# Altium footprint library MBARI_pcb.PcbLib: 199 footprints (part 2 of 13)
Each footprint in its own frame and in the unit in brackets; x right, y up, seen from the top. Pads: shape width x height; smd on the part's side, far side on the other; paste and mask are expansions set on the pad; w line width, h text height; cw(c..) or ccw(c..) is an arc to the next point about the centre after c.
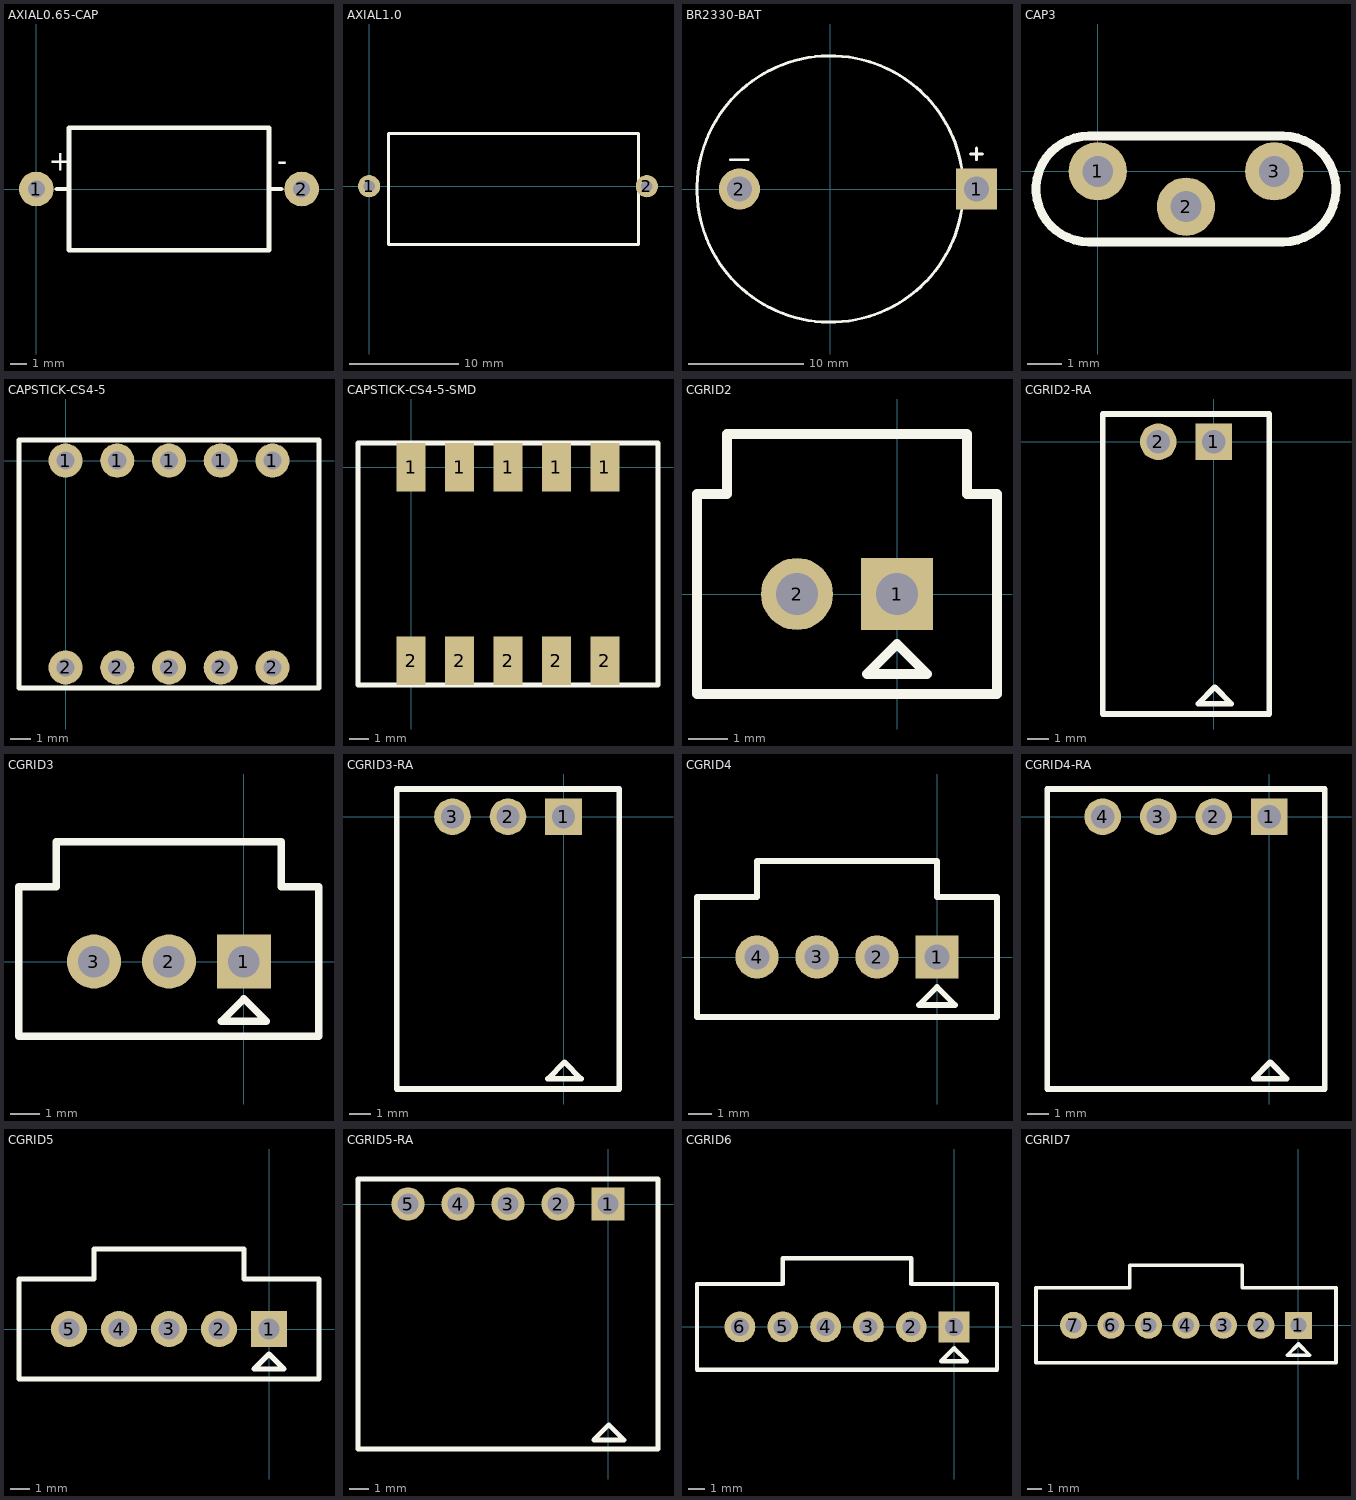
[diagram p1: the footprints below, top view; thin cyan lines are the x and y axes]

## AXIAL0.65-CAP [mil]
pads (2):
  round 85 hole 42: 1(0,0) 2(650,0)
TopOverlay:
  lines w10: 50,0 80,0 ; 570,0 600,0
  lines w12: 80,-150 570,-150 570,150 80,150 80,-150
  text "+" at 30,45 h50
  text "-" at 590,45 h50

## AXIAL1.0 [mil]
pads (2):
  round 80 hole 42: 1(0,0) 2(1000,0)
TopOverlay:
  lines w12: 70,-210 970,-210 970,190 70,190 70,-210

## BR2330-BAT [mil] "BR2330 lithium battery horiz mounted"
height 120
pads (2):
  rect 140x140 hole 86: 1(500,0)
  round 140 hole 86: 2(-310,0)
TopOverlay:
  circle w10: c0,0 r455
  lines w10: -340,100 -280,100 ; 480,120 500,120 520,120 ; 500,100 500,140

## CAP3 [mil]
pads (3):
  round 66 hole 35: 1(0,0) 2(100,-40) 3(200,0)
TopOverlay:
  lines w10: -10,-80 cw(c-10,-20) -10,40 210,40 cw(c210,-20) 210,-80 -10,-80

## CAPSTICK-CS4-5 [mil]
pads (10):
  round 66 hole 35: 1(0,0) 1(100,0) 1(200,0) 1(300,0) 1(400,0) 2(0,-400) 2(100,-400) 2(200,-400) 2(300,-400) 2(400,-400)
TopOverlay:
  lines w10: -90,-440 490,-440 490,40 -90,40 -90,-440

## CAPSTICK-CS4-5-SMD [mil]
pads (10):
  rect 60x100 smd: 1(0,0) 1(100,0) 1(200,0) 1(300,0) 1(400,0) 2(0,-400) 2(100,-400) 2(200,-400) 2(300,-400) 2(400,-400)
TopOverlay:
  lines w10: -110,-450 -110,50 510,50 510,-450 -110,-450

## CGRID2 [mil]
pads (2):
  rect 72x72 hole 42: 1(0,0)
  round 72 hole 42: 2(-100,0)
TopOverlay:
  lines w10: -200,-100 100,-100 100,100 70,100 70,160 -170,160 -170,100 -200,100 -200,-100 ; -30,-80 0,-50 30,-80 -30,-80

## CGRID2-RA [mil]
pads (2):
  rect 66x66 hole 42: 1(0,0)
  round 66 hole 42: 2(-100,0)
TopOverlay:
  lines w10: -200,-490 100,-490 100,50 -200,50 -200,-490 ; -28.29,-471.71 1.71,-441.71 31.71,-471.71 -28.29,-471.71

## CGRID3 [mil]
pads (3):
  rect 72x72 hole 42: 1(0,0)
  round 72 hole 42: 2(-100,0) 3(-200,0)
TopOverlay:
  lines w10: -300,-100 -300,100 -250,100 -250,160 50,160 50,100 100,100 100,-100 -300,-100 ; -30,-79.88 0,-49.88 30,-79.88 -30,-79.88

## CGRID3-RA [mil]
pads (3):
  rect 66x66 hole 42: 1(0,0)
  round 66 hole 42: 2(-100,0) 3(-200,0)
TopOverlay:
  lines w10: -300,-490 100,-490 100,50 -300,50 -300,-490 ; -28.29,-471.71 1.71,-441.71 31.71,-471.71 -28.29,-471.71

## CGRID4 [mil]
pads (4):
  rect 72x72 hole 42: 1(0,0)
  round 72 hole 42: 2(-100,0) 3(-200,0) 4(-300,0)
TopOverlay:
  lines w10: -400,-100 -400,100 -300,100 -300,160 0,160 0,100 100,100 100,-100 -400,-100 ; -30,-80 30,-80 0,-50 -30,-80

## CGRID4-RA [mil]
pads (4):
  rect 66x66 hole 42: 1(0,0)
  round 66 hole 42: 2(-100,0) 3(-200,0) 4(-300,0)
TopOverlay:
  lines w10: -400,-490 -400,50 100,50 100,-490 -400,-490 ; -28.29,-471.71 31.71,-471.71 1.71,-441.71 -28.29,-471.71

## CGRID5 [mil]
pads (5):
  rect 72x72 hole 42: 1(0,0)
  round 72 hole 42: 2(-100,0) 3(-200,0) 4(-300,0) 5(-400,0)
TopOverlay:
  lines w10: -500,-100 100,-100 100,100 -50,100 -50,160 -350,160 -350,100 -500,100 -500,-100 ; -30,-80 0,-50 30,-80 -30,-80

## CGRID5-RA [mil]
pads (5):
  rect 66x66 hole 42: 1(0,0)
  round 66 hole 42: 2(-100,0) 3(-200,0) 4(-300,0) 5(-400,0)
TopOverlay:
  lines w10: -500,-490 -500,50 100,50 100,-490 -500,-490 ; -28.29,-471.71 31.71,-471.71 1.71,-441.71 -28.29,-471.71

## CGRID6 [mil]
pads (6):
  rect 72x72 hole 42: 1(0,0)
  round 72 hole 42: 2(-100,0) 3(-200,0) 4(-300,0) 5(-400,0) 6(-500,0)
TopOverlay:
  lines w10: -600,-100 100,-100 100,100 -100,100 -100,160 -400,160 -400,100 -600,100 -600,-100 ; -30,-80 30,-80 0,-50 -30,-80

## CGRID7 [mil]
pads (7):
  rect 72x72 hole 42: 1(0,0)
  round 72 hole 42: 2(-100,0) 3(-200,0) 4(-300,0) 5(-400,0) 6(-500,0) 7(-600,0)
TopOverlay:
  lines w10: -700,-100 -700,100 -450,100 -450,160 -150,160 -150,100 100,100 100,-100 -700,-100 ; -30,-80 30,-80 0,-50 -30,-80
